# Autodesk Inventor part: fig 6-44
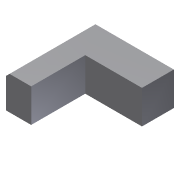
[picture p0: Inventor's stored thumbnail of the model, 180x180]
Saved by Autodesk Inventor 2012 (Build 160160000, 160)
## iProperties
Created: 2010-08
Part Number: fig 6-44
Document SubType Name: Modeling
Designer: CADSoft
Density: 1 g/cm^3
Material: Default
Author: CADSoft
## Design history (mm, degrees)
sketch "Sketch1"
  geometry: L1 (-33.983, 0)-(-48.97, 0); L2 (-48.97, 0)-(-48.97, 51.503); L3 (-48.97, 51.503)-(0, 51.503); L4 (0, 51.503)-(0, 32.411); L5 (-33.983, 0)-(-33.983, 32.411); L6 (-33.983, 32.411)-(0, 32.411); 1 further point
  constraints: 12 end point, 3 parallel, 2 perpendicular, 1 horizontal
extrude "Extrusion1" new body sketch "Sketch1" distance "d0" = 20; taper "d1" = 0 deg
chamfer "Chamfer1" distance "d2" = 2; stored, may be unused: second distance "d3" = 2, angle "d4" = 45 deg
body "Solid1"
